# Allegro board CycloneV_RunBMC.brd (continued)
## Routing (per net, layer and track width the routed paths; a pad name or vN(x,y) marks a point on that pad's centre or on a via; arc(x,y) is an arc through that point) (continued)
ULPI_USBPHY_USB2B_DATA<1>: length 53.7
  TOP w0.112: R405.2 55.08,18.57 54.97,18.68 v1(54.97,19.04)
  TOP w0.127: UT7.A5 v1(17.98,11.21)
  L10-SIG w0.076: v1(17.98,11.21) 18.38,11.61 18.38,12.17 18.09,12.47 17.84,12.47 17.54,12.76 17.54,14.43 17.29,14.69 17.29,16.19 18.43,17.34 18.43,17.84 18.66,18.07 19.02,18.07 19.24,18.28 19.24,18.66 19.78,19.21 35.22,19.21 35.63,19.61 40.48,19.61 40.84,19.97 42.54,19.97 42.97,20.4 46.96,20.4 47.36,20 47.82,20 48.99,21.16 49.88,21.16 50.23,21.52 56.46,21.52 56.76,21.21 56.76,19.39 56.42,19.04 v1(54.97,19.04)
ULPI_USBPHY_USB2B_DATA<2>: length 53.3
  TOP w0.112: v1(54.78,17.55) 55,17.55 55.29,17.84 R404.2
  TOP w0.127: v1(19.58,17.61) 19.58,17.61 UT7.C13
  L10-SIG w0.076: v1(19.58,17.61) 19.96,17.99 35.38,17.99 36.34,18.95 40.79,18.95 41,18.74 41.62,18.74 41.7,18.81 41.7,19.13 41.77,19.21 41.93,19.21 42,19.13 42,18.81 42.08,18.74 42.91,18.74 43.22,19.06 50.79,19.06 50.87,19.13 50.87,19.84 50.97,19.94 51.17,19.94 51.25,19.87 51.25,18.07 51.35,17.97 51.48,17.97 51.56,18.04 51.56,19.87 51.63,19.94 51.78,19.94 51.86,19.87 51.86,18.5 51.96,18.4 52.09,18.4 52.16,18.47 52.16,19.87 52.24,19.94 52.39,19.94 52.47,19.87 52.47,19.03 52.55,18.95 52.7,18.95 52.77,19.03 52.77,19.87 52.85,19.94 53,19.94 53.08,19.87 53.08,19.03 53.16,18.95 53.31,18.95 53.38,19.03 53.38,19.87 53.46,19.94 53.61,19.94 53.69,19.87 53.69,19.03 53.77,18.95 53.92,18.95 53.99,19.03 53.99,19.87 54.07,19.94 54.3,19.94 54.37,19.87 54.37,17.68 54.51,17.55 v1(54.78,17.55)
ULPI_USBPHY_USB2B_DATA<3>: length 54.2
  TOP w0.112: v1(54.96,17.05) 55.48,17.05 R403.2
  TOP w0.127: UT7.B6 v1(18.79,12.02)
  L10-SIG w0.076: v1(54.96,17.05) 55.37,17.05 55.49,17.18 55.49,18.41 55.37,18.54 54.79,18.54 54.6,18.73 54.6,19.23 54.76,19.39 56.31,19.39 56.46,19.54 56.46,20.88 56.1,21.24 50.39,21.24 50.01,20.86 49.09,20.86 47.95,19.72 47.21,19.72 46.79,20.14 43.14,20.14 42.77,19.77 41.07,19.77 40.68,19.39 35.76,19.39 35.35,18.98 20.36,18.98 19.92,18.54 19.92,18.27 19.72,18.07 19.55,18.07 19.2,17.71 19.2,17.54 18.92,17.27 18.75,17.27 17.95,16.46 17.94,16.46 17.53,16.06 17.53,14.8 18.36,13.98 18.36,12.65 18.79,12.22 v1(18.79,12.02)
ULPI_USBPHY_USB2B_DATA<4>: length 53
  TOP w0.112: R402.2 55.09,16.41 54.98,16.52 v1(54.96,16.52)
  TOP w0.127: UT7.H13 v1(23.59,17.62)
  L10-SIG w0.076: v1(23.59,17.62) 24.02,17.19 28.79,17.19 28.86,17.26 28.86,17.63 28.94,17.71 29.09,17.71 29.17,17.63 29.17,17.26 29.24,17.19 35.11,17.19 36.68,18.76 40.2,18.76 40.48,18.47 42.95,18.47 43.22,18.75 45.57,18.75 45.65,18.67 45.65,18.1 45.72,18.02 45.88,18.02 45.95,18.1 45.95,18.67 46.03,18.75 46.67,18.75 46.74,18.67 46.74,18.57 46.82,18.5 46.97,18.5 47.05,18.57 47.05,18.67 47.12,18.75 49.46,18.75 49.54,18.67 49.54,17.76 49.62,17.68 49.77,17.68 49.85,17.76 49.85,18.67 49.92,18.75 50.07,18.75 50.15,18.67 50.15,17.76 50.23,17.68 50.38,17.68 50.46,17.76 50.46,18.67 50.53,18.75 50.77,18.75 50.95,18.57 50.95,17.73 50.59,17.38 46.35,17.38 46.27,17.3 46.27,17.1 46.35,17.02 50.67,17.02 51.3,17.66 51.76,17.66 52.72,18.62 54.04,18.62 54.15,18.52 54.15,17.25 54.86,16.54 54.93,16.54 v1(54.96,16.52)
ULPI_USBPHY_USB2B_DATA<5>: length 55.3
  TOP w0.127: UT7.A4 v1(18.01,10.44)
  L10-SIG w0.076: v1(18.01,10.44) 17.54,10.9 17.54,12.31 17.27,12.59 17.27,14.36 17,14.62 17,16.19 18.21,17.4 18.21,17.96 18.38,18.14 18.38,18.55 19.25,19.41 35.1,19.41 36.15,20.46 39.38,20.46 39.74,20.83 40.95,20.83 41.34,21.23 43.2,21.23 43.35,21.38 44.94,21.38 45.26,21.06 47.87,21.06 48.35,21.54 49.78,21.54 50.06,21.82 54.6,21.82 v1(54.68,21.9)
  BOTTOM w0.112: R400.2 58.85,17.15 59.15,17.46 59.15,18.18 59.04,18.29 58.26,18.29 54.68,21.87 v1(54.68,21.9)
ULPI_USBPHY_USB2B_DATA<6>: length 52.7
  TOP w0.127: UT7.H12 v1(23.59,16.82)
  L10-SIG w0.076: v1(49.12,18.19) 48.69,17.76 45.51,17.76 44.79,18.48 43.36,18.48 43.1,18.22 41.55,18.22 41.32,17.99 36.65,17.99 35.05,16.39 24.02,16.39 v1(23.59,16.82)
  BOTTOM w0.112: v1(49.12,18.19) 49.12,19.35 49.33,19.56 50.14,19.56 50.25,19.45 50.25,18.34 50.43,18.16 50.59,18.16 50.7,18.27 50.7,19.45 50.81,19.56 51.03,19.56 51.14,19.45 51.14,18.3 51.26,18.19 51.45,18.19 51.59,18.33 51.59,19.45 51.7,19.56 51.93,19.56 52.04,19.45 52.04,18.23 52.15,18.12 52.31,18.12 52.49,18.3 52.49,19.45 52.6,19.56 53.63,19.56 53.74,19.68 53.74,21.57 54.48,22.31 55.13,22.31 55.24,22.2 55.24,21.72 58.34,18.62 59.18,18.62 59.48,18.32 59.48,17.48 59.61,17.35 R401.2
ULPI_USBPHY_USB2B_DATA<7>: length 59
  TOP w0.127: UT7.B4 v1(18.82,10.44)
  L10-SIG w0.076: v1(54.67,22.7) 54.13,22.17 49.93,22.17 49.68,21.91 44.58,21.91 44.27,21.6 41.07,21.6 40.63,21.16 36.42,21.16 34.87,19.61 19.17,19.61 18.12,18.56 18.12,18.3 17.95,18.14 17.95,17.43 16.44,15.92 16.44,13.48 16.91,13.01 16.91,12.54 17.34,12.1 17.34,10.44 17.75,10.04 18.31,10.04 18.71,10.44 v1(18.82,10.44)
  BOTTOM w0.112: v1(54.67,22.7) 54.72,22.7 54.73,22.71 55.14,22.71 55.62,22.23 55.62,21.75 58.41,18.95 59.25,18.95 59.8,18.41 59.8,17.75 60.37,17.18 R399.2
ULPI_USBPHY_USB2B_DIR: length 52
  TOP w0.112: v1(53.05,17.81) 53.38,18.14 53.38,19.84 55.06,21.52 R409.2
  TOP w0.127: UT7.B11 v1(19.58,16.01)
  L10-SIG w0.076: v1(53.05,17.81) 53.05,17.71 53.81,16.95 53.81,15.93 54.04,15.7 55.21,15.7 55.29,15.63 55.29,15.19 55.21,15.12 53.63,15.12 53.55,15.19 53.55,15.47 53.47,15.55 53.32,15.55 53.25,15.47 53.25,15.19 53.17,15.12 53.02,15.12 52.94,15.19 52.94,15.47 52.86,15.55 52.71,15.55 52.64,15.47 52.64,15.19 52.56,15.12 52.41,15.12 52.33,15.19 52.33,15.47 52.25,15.55 52.1,15.55 52.03,15.47 52.03,15.19 51.95,15.12 51.75,15.12 51.67,15.19 51.67,15.45 51.59,15.52 51.44,15.52 51.37,15.45 51.37,15.19 51.29,15.12 49.32,15.12 48.51,14.31 44.49,14.31 43.25,15.55 42.26,15.55 41.93,15.22 40.28,15.22 39.83,14.77 36.76,14.77 35.16,13.16 24.33,13.16 24.04,13.45 24.04,13.79 23.82,14 23.5,14 22.05,15.45 21.84,15.45 21.53,15.75 21.53,16.14 21.26,16.41 20.24,16.41 19.83,16.01 v1(19.58,16.01)
ULPI_USBPHY_USB2B_DIR_R: length 3.4
  TOP w0.104: EU12.31 58.94,21.04 58.33,21.65 57.01,21.65 56.88,21.52 R409.1
ULPI_USBPHY_USB2B_NXT: length 52.9
  TOP w0.112: v1(53.43,16.79) 53.51,16.79 54.22,17.51 54.22,19.69 54.73,20.2 55.4,20.2 R407.2
  TOP w0.127: UT7.B9 v1(18.81,14.44)
  L10-SIG w0.076: v1(53.43,16.79) 53.43,16.19 53.18,15.93 49.55,15.93 49.35,15.73 49.24,15.73 49.06,15.92 48.95,15.92 48.84,15.81 48.84,15.7 49.03,15.52 49.03,15.41 48.18,14.56 47.81,14.56 47.74,14.64 47.74,15.12 47.66,15.19 47.51,15.19 47.43,15.12 47.43,14.64 47.35,14.56 47.2,14.56 47.13,14.64 47.13,15.12 47.05,15.19 46.9,15.19 46.82,15.12 46.82,14.64 46.75,14.56 46.59,14.56 46.52,14.64 46.52,15.12 46.44,15.19 46.29,15.19 46.21,15.12 46.21,14.64 46.14,14.56 45.98,14.56 45.91,14.64 45.91,15.12 45.83,15.19 45.68,15.19 45.6,15.12 45.6,14.64 45.53,14.56 45.37,14.56 45.3,14.64 45.3,15.12 45.22,15.19 45.07,15.19 44.99,15.12 44.99,14.64 44.92,14.56 44.62,14.56 43.38,15.8 40.99,15.8 40.71,16.08 40.33,16.08 39.89,15.64 38.91,15.64 38.91,15.65 36.82,15.65 35.15,13.98 24.28,13.98 23.92,14.33 23.92,14.61 23.74,14.79 23.41,14.79 23.23,14.97 23.23,15.34 22.93,15.65 22.93,16.11 22.4,16.64 19.98,16.64 19.73,16.39 19.37,16.39 19.2,16.21 19.2,15.89 18.92,15.62 18.66,15.62 18.43,15.4 18.43,14.83 v1(18.81,14.44)
ULPI_USBPHY_USB2B_NXT_R: length 1.9
  TOP w0.127: EU12.2 57.16,19.31 57.04,19.44 57.04,19.89 56.89,20.05 R407.1
ULPI_USBPHY_USB2B_R_DATA<0>: length 1.6
  TOP w0.127: R406.1 56.75,19 57.02,19 57.21,18.82 EU12.3
ULPI_USBPHY_USB2B_R_DATA<1>: length 1.5
  TOP w0.127: EU12.4 57.15,18.31 56.89,18.57 R405.1
ULPI_USBPHY_USB2B_R_DATA<2>: length 1.4
  TOP w0.127: R404.1 57.19,17.84 57.21,17.82 EU12.5
ULPI_USBPHY_USB2B_R_DATA<3>: length 1.4
  TOP w0.127: EU12.6 57.08,17.31 56.89,17.13 R403.1
ULPI_USBPHY_USB2B_R_DATA<4>: length 1.6
  TOP w0.127: R402.1 56.94,16.41 57.07,16.54 57.07,16.69 57.19,16.82 EU12.7
ULPI_USBPHY_USB2B_R_DATA<5>: length 1.8
  TOP w0.104: v1(58.36,14.92) 58.36,15.02 58.44,15.1 EU12.9
  BOTTOM w0.112: v1(58.36,14.92) 58.36,15.25 R400.1
ULPI_USBPHY_USB2B_R_DATA<6>: length 1.8
  TOP w0.104: EU12.10 58.94,15.02 58.97,14.99 v1(58.97,14.95)
  BOTTOM w0.112: R401.1 59.61,15.68 58.97,15.04 v1(58.97,14.95)
ULPI_USBPHY_USB2B_R_DATA<7>: length 1.4
  TOP w0.104: EU12.13 v1(60.44,15.02)
  BOTTOM w0.112: v1(60.44,15.02) 60.44,15.66 R399.1
ULPI_USBPHY_USB2B_STP: length 54.7
  TOP w0.104: v1(59.94,21.49) 59.94,21.49 EU12.29
  TOP w0.127: UT7.B8 v1(18.79,13.62)
  L10-SIG w0.076: v1(59.94,21.49) 59.94,19.89 56.05,16.01 54.84,16.01 54.58,16.26 54.58,16.49 53.79,17.28 53.79,17.94 53.54,18.19 52.65,18.19 51.8,17.34 51.36,17.34 50.72,16.69 46.2,16.69 45.55,17.34 44.71,17.34 44.53,17.52 43.36,17.52 43.02,17.18 36.24,17.18 34.69,15.63 24.22,15.63 24.02,15.83 24.02,16.08 23.64,16.46 23.34,16.46 23.06,16.74 23.06,16.95 22.78,17.23 19.46,17.23 19.21,16.98 19.21,16.74 18.92,16.45 18.67,16.45 18.26,16.03 18.26,14.46 18.79,13.92 v1(18.79,13.62)
  BOTTOM w0.112: R410.2 v1(59.94,21.49)
UNNAMED_60_MPM3632_I11_OUTSENSE: length 1.5
  TOP w0.254: UT8.10 5.84,17.33 6.32,17.81 RT69.1
UNNAMED_60_MPM3632_I18_OUTSENSE: length 1.7
  TOP w0.254: UT5.10 5.84,22.92 v2(6.15,23.23)
  BOTTOM w0.508: v2(6.15,23.23) 6.13,23.24 RB81.1
UNNAMED_61_MPM3833_I38_OUTS: length 1.2
  TOP w0.203: RT66.1 12.49,19.08 12.72,19.31 UT6.3
USB2_PCH_SMC_DN: length 12.2
  TOP w0.091: v1(56.94,6.12) 56.95,6.12 56.95,6.1 56.97,6.07 56.97,6.03 57.04,5.96 57.04,3.3 57.43,2.92 JT3.217 ; U8A6.19 59.98,9.57 59.99,9.56 60.44,9.56 60.8,9.2 60.8,8.28 60.29,7.77 60.29,7.27 60.17,7.15 60.17,7.12 60.07,7.02 v1(60.07,6.71)
  L3-SIG w0.091: v1(56.94,6.12) 57.04,6.21 59.48,6.21 59.98,6.71 v1(60.07,6.71)
USB2_PCH_SMC_DP: length 12.1
  TOP w0.091: v1(59.76,7.24) 59.83,7.24 59.99,7.4 59.99,7.9 60.5,8.41 60.5,9.07 60.31,9.25 60.12,9.25 59.93,9.07 U8A6.18 ; JT3.219 57.93,2.99 57.84,3.08 57.72,3.08 57.71,3.1 57.71,3.1 57.49,3.32 57.49,3.32 57.35,3.46 57.35,4.71 57.47,4.83 57.47,5.11 57.35,5.23 57.35,5.4 57.47,5.52 57.47,5.72 57.37,5.82 57.37,6.44 57.26,6.56 57.09,6.56 v1(57,6.65)
  L3-SIG w0.091: v1(57,6.65) 57.02,6.63 59.31,6.63 59.76,7.09 v1(59.76,7.24)
USB2_USB2B_DN: length 18.9
  TOP w0.091: JT3.223 58.93,2.85 59.02,2.95 59.02,5.24 59.51,5.72 59.94,5.72 61.08,6.87 v1(61.08,7.02)
  TOP w0.104: v1(63.27,17.23) 63.24,17.23 63.15,17.31 EU12.19
  L5-SIG w0.074: v1(61.08,7.02) 61.26,7.19 61.26,12.17 61.79,12.71 61.79,16.64 62.27,17.12 62.55,17.12 62.81,17.12 62.92,17.23 v1(63.27,17.23)
USB2_USB2B_DP: length 18.6
  TOP w0.091: JT3.225 59.43,2.85 59.33,2.95 59.33,5.11 59.63,5.42 60.06,5.42 61.66,7.02 v1(61.68,7.02)
  TOP w0.104: v1(63.26,16.69) 63.26,16.71 63.16,16.82 EU12.18
  L5-SIG w0.074: v1(61.68,7.02) 61.56,7.13 61.56,12.05 62.1,12.58 62.1,16.52 62.39,16.81 62.54,16.81 62.81,16.81 62.92,16.7 v1(63.26,16.69)
V_BMC_DAC_IOB: length 131.2
  TOP w0.104: v1(50.54,23.63) 50.95,23.22 50.95,21.29 51.12,21.11 R423.2 R417.2 R424.2 R420.2 53.69,20.66 53.48,20.45 52.87,20.45 52.67,20.25 R429.1
  L5-SIG w0.076: v1(50.54,23.63) 49.47,23.63 49.02,24.08 49.02,34.44 48.52,34.94 48.52,37.43 47.72,38.23 47.72,47.61 46.91,48.42 2.89,48.42 1.03,46.56 1.03,26.35 3.52,23.86 4.72,23.86 4.98,23.61 4.98,15.76 3.37,14.15 3.37,6.94 4.01,6.3 4.01,5.59 3.42,5.01 v1(3.42,3.94)
  BOTTOM w0.112: JT3.12 4.18,2.66 4.64,3.12 4.64,3.97 4.32,4.29 3.65,4.29 3.42,4.07 v1(3.42,3.94)
V_BMC_DAC_IOG: length 130.1
  TOP w0.104: v1(49.12,20.4) 48.94,20.4 48.75,20.21 48.75,19.5 48.25,19 ; R428.2 R422.2 R427.2 R419.2 49.16,19 48.25,19 ; R431.1 48.25,19
  L5-SIG w0.076: v1(3.98,3.89) 4.37,3.89 4.69,4.21 4.69,6 3.63,7.07 3.63,14.05 5.23,15.65 5.23,23.7 4.82,24.1 3.99,24.1 3.4,24.69 3.4,26.37 3.04,26.73 3.04,31.85 2.47,32.42 2.47,34.56 1.31,35.72 1.31,46.37 3.06,48.11 46.63,48.11 47.48,47.26 47.48,38.13 48.22,37.4 48.22,34.79 48.8,34.21 48.8,27.15 47.97,26.32 47.97,22.69 49.12,21.54 v1(49.12,20.4)
  BOTTOM w0.112: v1(3.98,3.89) 4.01,3.87 4.01,3.86 4.37,3.5 4.37,3.18 4.14,2.96 3.85,2.96 3.68,2.78 JT3.10
V_BMC_DAC_IOR: length 125.4
  TOP w0.104: v1(47.64,21.42) 47.64,21.39 47.92,21.11 R421.2 ; R426.2 R425.2 R418.2 R421.2 ; R430.1 48.22,21.1 R421.2
  L5-SIG w0.076: v1(5.35,5.19) 5.35,5.75 3.88,7.22 3.88,13.96 5.47,15.56 5.47,23.72 5.66,23.91 5.66,24.9 5.25,25.3 5.25,26.4 3.3,28.35 3.3,31.94 2.71,32.52 2.71,42.96 1.54,44.13 1.54,46.26 3.09,47.81 46.32,47.81 47.24,46.89 47.24,38.44 47.22,38.43 47.22,38.05 47.95,37.32 47.95,29.09 47.36,28.5 47.36,21.67 47.62,21.42 v1(47.64,21.42)
  BOTTOM w0.112: v1(5.35,5.19) 5.08,5.19 4.9,5 4.9,3.04 4.68,2.82 JT3.14
V_BMC_DDC_SCL: length 52.8
  TOP w0.127: UT7.W24 v1(32.33,26.36)
  L8-SIG w0.076: v1(6.19,4.55) 6.7,5.06 7.79,5.06 7.99,4.86 8.78,4.86 9.11,5.19 9.11,6.83 9.92,7.64 9.92,11.46 10.61,12.15 10.61,12.4 11.32,13.11 11.32,15.12 13.4,17.2 13.4,21.21 15.12,22.92 19.35,22.92 19.43,22.85 23.75,22.85 23.97,23.07 23.97,23.31 24.29,23.63 24.51,23.63 24.8,23.92 24.8,24.14 25.83,25.17 25.84,25.17 26.89,26.22 28.49,26.22 29.05,26.78 31.91,26.78 v1(32.33,26.36)
  BOTTOM w0.089: v1(32.33,26.36) 32.33,26.42 32.68,26.78 33.55,26.78 33.61,26.84 33.61,30.7 33.55,30.76
  BOTTOM w0.112: JT3.20 6.18,2.89 6.52,3.23 6.52,3.25 6.58,3.31 6.58,4.17 v1(6.19,4.55) ; 33.55,30.76 33.45,30.87 R433.2
V_BMC_DDC_SDA: length 54
  TOP w0.127: UT7.AB25 v1(34.78,27.21)
  L8-SIG w0.076: v1(6.22,5.11) 6.37,5.26 7.89,5.26 8.1,5.06 8.68,5.06 8.91,5.29 8.91,6.92 9.72,7.73 9.72,11.33 9.43,11.63 9.43,13.26 10.99,14.82 10.99,15.29 12.13,16.44 12.13,20.23 15.32,23.41 18.11,23.41 18.31,23.6 23.68,23.6 24.02,23.93 24.02,24.16 24.25,24.39 24.66,24.39 26.92,26.65 28.57,26.65 29.51,27.59 33.85,27.59 33.85,27.59 34.15,27.59 34.15,27.59 34.4,27.59 v1(34.78,27.21)
  BOTTOM w0.089: v1(34.78,27.21) 34.38,27.61 34.38,30.67 34.28,30.76
  BOTTOM w0.112: v1(6.22,5.11) 6.6,4.73 6.6,4.51 6.82,4.28 6.82,3.15 6.68,3.01 JT3.22 ; R432.2 34.21,30.84 34.28,30.76
V_BMC_HSYN: length 28.9
  L5-SIG w0.076: v1(14.22,5.31) 14.13,5.31 13.99,5.16 13.58,5.16 12.93,4.51 12.93,3.18 12,2.24 6.26,2.24 5.56,2.94 v1(5.56,3.33)
  BOTTOM w0.112: JT3.16 5.18,2.94 v1(5.56,3.33)
  BOTTOM w0.114: v1(14.22,5.31) 14.27,5.35 14.27,5.49 14.34,5.57 14.34,5.59 14.65,5.9 14.65,6.74 15.41,7.5 15.41,8.64 16.16,9.39 17.37,9.39 17.54,9.57 17.54,10.56 17.83,10.85 18.93,10.85 19.18,11.09 19.18,16.08 18.82,16.44 18.61,16.44 R415.2
V_BMC_HSYN_R: length 6
  TOP w0.089: UT7.E11 v1(21.97,16.01)
  BOTTOM w0.114: R415.1 18.15,17.81 18.38,18.04 19.83,18.04 20.01,17.86 20.01,17.47 20.27,17.2 21.51,17.2 21.97,16.74 v1(21.97,16.01)
V_BMC_VSYN: length 29.2
  L5-SIG w0.076: v1(14.83,5.31) 14.45,5.69 14.03,5.69 13.77,5.43 12.27,5.43 11.86,5.02 11.86,3.18 11.3,2.62 6.85,2.62 6.14,3.33 v1(6.14,3.42)
  BOTTOM w0.112: JT3.18 5.68,2.87 6.14,3.33 v1(6.14,3.42)
  BOTTOM w0.114: v1(14.83,5.31) 14.83,5.7 14.9,5.78 14.9,6.18 15.06,6.33 15.59,6.33 15.72,6.46 15.72,8.58 16.29,9.15 17.62,9.15 18.46,9.99 19.91,9.99 20.01,10.09 20.01,16.36 20.26,16.62 R416.2
V_BMC_VSYN_R: length 1.2
  TOP w0.089: UT7.D11 v1(21.17,16.02)
  BOTTOM w0.114: R416.1 21.15,16.03 v1(21.17,16.02)
V_M_BMC_DDR3_BA0: length 54.5
  TOP w0.127: U4.M2 v1(42.55,43.16) ; UT7.A27 18.07,29.52 v1(17.39,29.52) ; U3.M2 v1(32.77,43.21) ; U2.M2 v1(22.93,43.23)
  L3-SIG w0.076: v1(17.39,29.52) 16.94,29.97 16.94,31.11 16.48,31.58 16.48,33 16.07,33.41 16.07,37.95 15.98,38.04 15.68,38.04 15.59,38.13 15.59,38.31 15.68,38.4 15.98,38.4 16.07,38.49 16.07,38.67 15.98,38.75 15.68,38.75 15.59,38.84 15.59,39.02 15.68,39.11 15.98,39.11 16.07,39.2 16.07,39.55 15.7,39.92 15.7,42.28 16.27,42.86 19.38,42.86 19.46,42.94 19.46,43.38 19.55,43.46 19.73,43.46 19.82,43.38 19.82,42.94 19.91,42.86 20.79,42.86 20.87,42.94 20.87,43.22 20.96,43.31 21.14,43.31 21.23,43.22 21.23,42.94 21.32,42.86 22.55,42.86 v1(22.93,43.23) 23.38,42.78 32.35,42.78 v1(32.77,43.21) 33.17,42.8 42.19,42.8 v1(42.55,43.16)
  BOTTOM w0.112: v1(42.55,43.16) 42.16,42.78 41.13,42.78 40.68,43.22 40.68,47.95 RB6.1
V_M_BMC_DDR3_BA1: length 59.5
  TOP w0.127: U4.N8 v1(36.95,43.96) ; v1(23.58,28.03) 23.58,28.01 UT7.H25 ; U2.N8 v1(17.33,44.03) ; U3.N8 v1(27.17,44.01)
  L10-SIG w0.076: v1(23.58,28.03) 23.23,28.38 23.23,29.91 23.02,30.12 21.88,30.12 21.74,30.26 21.74,30.89 21.56,31.07 21.08,31.07 20.54,31.6 20.54,37.78 20.45,37.86 19.59,37.86 19.5,37.95 19.5,38.13 19.59,38.22 20.45,38.22 20.54,38.31 20.54,38.49 20.45,38.58 19.49,38.58 19.4,38.66 19.4,38.84 19.49,38.93 20.45,38.93 20.54,39.02 20.54,39.2 20.45,39.29 19.41,39.29 19.32,39.38 19.32,39.55 19.41,39.64 20.45,39.64 20.54,39.73 20.54,39.95 20.45,40.04 16.2,40.04 15.82,40.42 15.82,43.95 16.26,44.39 16.96,44.39 v1(17.33,44.03) 17.68,44.38 18.87,44.38 19.65,43.59 26.76,43.59 v1(27.17,44.01) 27.58,43.6 36.59,43.6 v1(36.95,43.96)
  BOTTOM w0.112: RB11.1 37.56,47.83 37.74,47.66 37.97,47.66 38.66,46.97 38.68,46.97 39.01,46.63 39.01,45.43 37.94,44.35 37.34,44.35 v1(36.95,43.96)
V_M_BMC_DDR3_BA2: length 58.2
  TOP w0.127: U3.M3 v1(31.97,43.21) ; v1(22.8,28.03) 22.8,27.99 UT7.G25 ; U2.M3 v1(22.13,43.23) ; U4.M3 v1(41.75,43.16)
  L8-SIG w0.076: v1(41.75,43.16) 41.37,42.79 32.39,42.79 v1(31.97,43.21) 31.6,42.83 22.52,42.83 v1(22.13,43.23) 21.55,43.23 21.25,42.93 21.25,41.23 21.71,40.77 21.71,40.47 21.82,40.35 22.79,40.35 22.9,40.24 22.9,40.01 22.79,39.89 21.82,39.89 21.71,39.78 21.71,39.02 21.89,38.84 22.42,38.84 22.52,38.74 22.52,38.14 22.41,38.03 21.81,38.03 21.71,37.93 21.71,37.37 21.84,37.24 22.45,37.24 22.55,37.14 22.55,36.58 22.4,36.43 21.75,36.43 21.6,36.28 21.06,36.28 20.95,36.16 20.95,35.76 21.06,35.64 22.41,35.64 22.52,35.53 22.52,34.97 22.41,34.85 21.06,34.85 20.95,34.74 20.95,34.13 21.06,34.02 22.82,34.02 22.93,33.9 22.93,33.09 22.82,32.97 21.06,32.97 20.95,32.86 20.95,32.03 20.11,31.2 20.11,30.41 20.8,29.72 20.8,29.47 21.08,29.19 22.26,29.19 22.37,29.08 22.37,28.38 22.72,28.03 v1(22.8,28.03)
  BOTTOM w0.112: RB5.1 41.12,47.58 40.95,47.41 40.95,44.46 40.96,44.45 40.96,43.95 v1(41.75,43.16)
V_M_BMC_DDR3_CAS_N: length 50.9
  TOP w0.127: v1(17.96,28.83) 17.96,28.81 18.36,28.41 UT7.A26 ; U4.K3 v1(41.75,41.56) ; U2.K3 v1(22.13,41.63) ; U3.K3 v1(31.97,41.61)
  L3-SIG w0.076: v1(41.75,41.56) 41.33,41.98 32.35,41.98 v1(31.97,41.61) 31.55,42.03 22.53,42.03 v1(22.13,41.63) 21.74,42.02 21.29,42.02 21.2,42.11 21.2,42.36 21.11,42.45 20.93,42.45 20.84,42.36 20.84,41.93 20.75,41.84 20.62,41.84 20.53,41.93 20.53,42.32 20.4,42.45 20.22,42.45 20.13,42.36 20.13,41.93 20.04,41.84 19.86,41.84 19.77,41.93 19.77,42.41 19.69,42.5 19.51,42.5 19.42,42.41 19.42,42.11 19.33,42.02 16.27,42.02 16.12,41.86 16.12,40.24 16.95,39.41 16.95,38.29 17.04,38.21 17.18,38.21 17.27,38.12 17.27,37.94 17.18,37.85 17.04,37.85 16.95,37.76 16.95,37.58 17.04,37.49 17.18,37.49 17.27,37.41 17.27,37.23 17.18,37.14 17.04,37.14 16.95,37.05 16.95,36.87 17.04,36.78 17.18,36.78 17.27,36.69 17.27,36.52 17.18,36.43 17.04,36.43 16.95,36.34 16.95,36.16 17.04,36.07 17.18,36.07 17.27,35.98 17.27,35.81 17.18,35.72 17.04,35.72 16.95,35.63 16.95,35.45 17.04,35.36 17.18,35.36 17.27,35.27 17.27,35.09 17.18,35.01 17.04,35.01 16.95,34.92 16.95,32.48 17.32,32.11 17.32,30.14 17.96,29.49 v1(17.96,28.83)
  BOTTOM w0.112: RB40.1 43.97,42.4 43.52,41.95 42.13,41.95 v1(41.75,41.56)
V_M_BMC_DDR3_CKE: length 61
  TOP w0.127: UT7.L28 26,30.39 v1(26,30.41) ; U2.K9 v1(16.53,41.63) ; U3.K9 v1(26.37,41.61) ; U4.K9 v1(36.15,41.56)
  L10-SIG w0.076: v1(26,30.41) 25.73,30.67 25.73,31.16 25.11,31.78 22.04,31.78 21.74,32.09 21.74,34.7 21.84,34.8 22.45,34.8 22.55,34.91 22.55,35.54 22.45,35.64 21.58,35.64 21.46,35.77 21.46,36.28 21.61,36.43 22.37,36.43 22.5,36.56 22.5,37.11 22.37,37.24 21.63,37.24 21.48,37.39 21.48,37.92 21.57,38 22.41,38 22.5,38.09 22.5,38.78 22.41,38.87 21.56,38.87 21.43,38.99 21.43,39.76 21.58,39.91 24.07,39.91 24.28,40.11 24.28,40.37 24.17,40.47 21.43,40.47 20.64,41.26 16.9,41.26 v1(16.53,41.63) 16.94,42.04 21.18,42.04 21.98,41.24 26.01,41.24 v1(26.37,41.61) 26.78,41.19 33.73,41.19 33.75,41.18 35.76,41.18 v1(36.15,41.56)
  BOTTOM w0.112: RB20.1 RB19.1 33.24,47.16 33.33,47.08 34,47.08 34.56,46.51 34.56,43.15 v1(36.15,41.56)
V_M_BMC_DDR3_CLK_DN: length 56.6
  TOP w0.122: v1(18.93,41.63) U2.K7 ; U3.K7 v1(28.77,40.81)
  TOP w0.127: U4.K7 v1(38.55,40.76) ; UT7.N20 v1(27.58,24.01)
  L5-SIG w0.076: 17.62,30.03 17.69,30.03 18.23,29.49 18.23,29.04 18.3,28.97 18.3,28.53 18.5,28.33 19.18,28.33 19.98,27.53 22.12,27.53 22.98,26.68 23.23,26.68 23.31,26.6 23.31,26.35 23.48,26.18 23.83,26.18 24,26.35 24,26.6 24.07,26.68 24.67,26.68 25.01,26.33 25.01,25.48 25.32,25.18 27.04,25.18 27.12,25.1 27.12,24.4 27.3,24.21 27.49,24.21 27.58,24.13 v1(27.58,24.01)
  L5-SIG w0.094: v1(38.55,40.76) 38.38,40.59 37.36,40.59 37.08,40.32 29.26,40.32 v1(28.77,40.81) 28.41,40.44 21.6,40.44 20.61,41.43 19.12,41.43 v1(18.93,41.63) 18.76,41.46 18.06,41.46 17.85,41.25 17.85,39.85 17.75,39.76 17.18,39.76 17.06,39.88 17.06,40.16 16.8,40.42 16.08,40.42 15.54,39.88 15.54,30.09 15.98,29.65 16.59,29.65 16.97,30.03 17.62,30.03
  BOTTOM w0.119: RB47.2 39.38,40.89 39.03,40.54 38.77,40.54 v1(38.55,40.76)
V_M_BMC_DDR3_CLK_DP: length 57
  TOP w0.127: U4.J7 v1(38.55,39.96) ; U3.J7 v1(28.77,40.01) ; U2.J7 v1(18.93,40.83) ; UT7.N21 v1(27.58,24.81)
  L5-SIG w0.076: v1(27.58,24.81) 27.77,24.61 27.77,24.43 27.71,24.36 27.37,24.36 27.27,24.46 27.27,25.28 27.12,25.43 26.94,25.43 26.84,25.33 26.64,25.33 26.51,25.45 26.41,25.45 26.28,25.33 26.05,25.33 25.9,25.48 25.77,25.48 25.62,25.33 25.38,25.33 25.16,25.54 25.16,25.76 25.29,25.89 25.29,26.04 25.16,26.17 25.16,26.55 25.04,26.68 24.89,26.68 24.73,26.83 24.01,26.83 23.84,26.66 23.84,26.41 23.77,26.33 23.54,26.33 23.46,26.41 23.46,26.66 23.3,26.83 23.04,26.83 22.19,27.68 20.04,27.68 19.24,28.48 18.56,28.48 18.45,28.59 18.45,29.03 18.38,29.1 18.38,29.55 17.8,30.14 17.8,30.18 17.72,30.26 17.62,30.26
  L5-SIG w0.094: v1(38.55,39.96) 38.55,40.04 38.22,40.37 37.45,40.37 37.17,40.09 29.24,40.09 29.16,40.01 v1(28.77,40.01) 28.57,40.21 21.51,40.21 20.52,41.2 19.3,41.2 v1(18.93,40.83) 18.57,41.18 18.15,41.18 18.08,41.1 18.08,39.76 17.85,39.53 17.09,39.53 16.83,39.78 16.83,40.06 16.71,40.19 16.17,40.19 15.77,39.78 15.77,30.18 16.07,29.88 16.5,29.88 16.88,30.26 17.62,30.26
  BOTTOM w0.119: RB47.1 39.22,40 39.01,40.21 38.8,40.21 v1(38.55,39.96)
V_M_BMC_DDR3_CS_N: length 58.6
  TOP w0.127: U4.L2 v1(42.55,42.36) ; U3.L2 v1(32.77,42.41) ; UT7.L21 v1(25.98,24.81) ; U2.L2 v1(22.93,42.43)
  L5-SIG w0.076: v1(42.55,42.36) 42.13,42.78 33.15,42.78 v1(32.77,42.41) 32.35,42.83 23.33,42.83 v1(22.93,42.43) 22.55,42.8 16.38,42.8 15.11,41.53 15.11,29.57 17.83,26.85 17.99,26.85 18.03,26.8 21.3,26.8 21.62,26.48 21.62,26.26 21.88,25.99 23.71,25.99 24.07,25.63 24.07,25.45 24.32,25.2 24.61,25.2 25,24.81 v1(25.98,24.81)
  BOTTOM w0.112: v1(42.55,42.36) 42.93,42.75 43.51,42.75 43.69,42.93 RB39.1
V_M_BMC_DDR3_DM_0: length 25.3
  TOP w0.127: v1(23.59,30.87) 23.59,30.42 UT7.G28 ; U2.E7 18.75,37.23 v1(19.17,37.65)
  L3-SIG w0.076: v1(19.17,37.65) 20.12,37.65 20.21,37.73 20.21,38.63 20.3,38.72 20.55,38.72 20.64,38.63 20.64,38.42 20.73,38.33 20.91,38.33 21,38.42 21,38.74 21.1,38.84 22.35,38.84 22.57,39.07 22.57,39.43 22.9,39.76 24.83,39.76 24.94,39.65 24.94,39.39 25,39.32 25.24,39.32 25.34,39.43 25.34,39.68 25.42,39.76 25.89,39.76 25.98,39.67 25.98,39.08 25.89,38.99 25.38,38.99 25.29,38.91 25.29,31.5 25.39,31.4 25.39,30.92 24.76,30.28 24.76,29.39 24.58,29.22 24.15,29.22 24,29.37 24,30.46 v1(23.59,30.87)
V_M_BMC_DDR3_DM_1: length 21.8
  TOP w0.127: U2.D3 v1(21.31,36.84) ; UT7.P28 v1(28.38,30.41)
  L5-SIG w0.076: v1(28.38,30.41) 28.38,30.52 28.67,30.82 28.67,30.9 28.86,31.09 28.86,31.49 29.91,32.54 29.91,37.88 29.79,38 25.69,38 25.57,38.12 25.57,38.73 25.46,38.84 25.23,38.84 25.12,38.73 25.12,38.12 25,38 24.77,38 24.66,38.12 24.66,38.75 24.55,38.87 24.32,38.87 24.2,38.75 24.2,38.12 24.09,38 21.63,38 21.31,37.68 v1(21.31,36.84)
V_M_BMC_DDR3_DM_2: length 24.2
  TOP w0.127: v1(33.15,30.41) 32.78,30.03 UT7.W28 ; v1(28.82,37.63) 28.4,37.2 U3.E7
  L10-SIG w0.076: v1(33.15,30.41) 34.88,32.14 35.32,32.14 36.59,33.41 36.59,39.43 36.44,39.58 35.55,39.58 35.46,39.67 35.46,40.3 35.37,40.39 35.19,40.39 35.11,40.3 35.11,39.44 35.02,39.35 34.84,39.35 34.75,39.44 34.75,40.3 34.66,40.39 34.48,40.39 34.39,40.3 34.39,39.67 34.31,39.58 31.97,39.58 31.62,39.22 29.84,39.22 28.82,38.2 v1(28.82,37.63)
V_M_BMC_DDR3_DM_3: length 23.7
  TOP w0.127: UT7.AB28 35.18,30.82 v1(34.8,31.2) ; U3.D3 31.98,36.81 v1(33.6,36.81)
  L3-SIG w0.076: v1(33.6,36.81) 33.14,37.27 33.14,37.8 32.96,37.98 31.74,37.98 31.59,38.13 31.59,38.69 31.69,38.79 32.89,38.79 33.14,39.05 33.14,39.68 33.42,39.96 34.75,39.96 34.83,39.87 34.83,39.03 34.92,38.94 35.1,38.94 35.19,39.03 35.19,39.87 35.28,39.96 35.57,39.96 35.65,39.87 35.65,39.1 35.99,38.77 36.16,38.77 36.52,38.41 36.52,33.43 36.09,33 35.91,33 34.8,31.89 v1(34.8,31.2)
V_M_BMC_DDR3_DM_4: length 33.2
  TOP w0.127: v1(40.62,36.73) 40.62,33.05 40.49,32.92 38.67,32.92 38.54,33.05 38.54,36.77 U4.E7 ; UT7.AE28 v1(37.17,30.42)
  L5-SIG w0.076: v1(37.17,30.42) 37.44,30.14 37.52,30.14 37.66,30 39.72,30 40.51,30.79 40.51,31.25 40.63,31.37 40.92,31.37 41.04,31.25 41.04,30.9 41.15,30.79 41.43,30.79 41.55,30.9 41.55,31.25 41.67,31.37 41.88,31.37 42,31.25 42,30.89 42.15,30.74 42.31,30.74 42.46,30.89 42.46,32.29 42.13,32.62 41.19,32.62 41.09,32.72 41.09,32.97 41.24,33.13 42.02,33.13 42.13,33.24 42.13,33.89 42.03,33.99 41.2,33.99 41.12,34.07 41.12,34.65 41.22,34.75 42.84,34.75 42.94,34.85 42.94,36.58 42.82,36.71 42.28,36.71 42.16,36.58 42.16,35.69 42,35.54 40.96,35.54 40.62,35.89 v1(40.62,36.73)
V_M_BMC_DDR3_DQ<0>: length 30.2
  TOP w0.127: U2.E3 v1(22.13,36.83) ; UT7.J25 v1(24.38,28.01)
  L3-SIG w0.076: v1(22.13,36.83) 22.31,36.83 22.73,37.24 23.95,37.24 24.1,37.09 24.1,32.49 23.08,31.48 22.71,31.48 22.62,31.39 22.62,30.54 22.78,30.38 23.62,30.38 23.67,30.33 23.67,30.05 23.59,29.98 22.94,29.98 22.85,29.89 22.85,29.37 23.01,29.22 23.84,29.22 23.97,29.09 23.97,28.5 23.89,28.43 23.31,28.43 23.2,28.31 23.2,27.68 23.31,27.56 24.22,27.56 25.09,26.7 25.39,26.7 25.98,26.12 25.98,25.27 26.07,25.18 26.28,25.18 26.41,25.05 26.41,23.61 26.5,23.53 27.06,23.53 27.15,23.61 27.15,25.57 27.06,25.66 26.76,25.66 26.64,25.79 26.64,26.22 26.03,26.83 25.8,26.83 25.62,27.01 25.62,27.5 25.53,27.59 24.8,27.59 v1(24.38,28.01)
V_M_BMC_DDR3_DQ<1>: length 29.8
  TOP w0.127: U2.F7 v1(18.95,38.45) ; UT7.J24 24.5,26.53 24.5,26.37 v1(24.43,26.29)
  L3-SIG w0.076: v1(24.43,26.29) 24.83,25.89 24.83,24.45 24.75,24.36 24.11,24.36 24.02,24.45 24.02,25.89 23.89,26.02 23.22,26.02 23.13,25.93 23.13,24.02 23.04,23.93 22.87,23.93 22.78,24.02 22.78,25.56 22.39,25.96 21.86,25.96 21.63,26.19 21.63,26.55 21.66,26.58 21.66,26.8 21.58,26.88 21.58,29.95 21.3,30.23 20.85,30.23 20.64,30.43 20.64,30.92 20.69,30.97 20.69,31.58 20.19,32.09 20.19,37.04 20.01,37.22 18.97,37.22 18.79,37.39 18.79,37.85 18.99,38.05 19.78,38.05 19.88,38.16 19.88,39.29 19.79,39.38 19.54,39.38 19.45,39.29 19.45,38.58 19.33,38.45 v1(18.95,38.45)
V_M_BMC_DDR3_DQ<2>: length 25.6
  TOP w0.127: U2.F2 v1(22.93,37.63) ; v1(22.21,30.69) 21.71,30.69 21.58,30.57 UT7.E28
  L3-SIG w0.076: v1(22.93,37.63) 22.73,37.63 22.29,37.19 21.77,37.19 21.68,37.1 21.68,36.53 21.77,36.44 23.27,36.44 23.36,36.35 23.36,34.14 23.21,33.99 22.95,33.99 22.88,33.91 22.88,33.72 22.97,33.64 23.3,33.64 23.39,33.55 23.39,33.34 23.3,33.25 22.65,33.25 22.5,33.41 22.5,35.58 22.41,35.67 21.86,35.67 21.74,35.79 21.74,36.02 21.66,36.1 21.39,36.1 21.33,36.04 21.33,35.4 21.42,35.31 21.6,35.31 21.68,35.22 21.68,33.64 21.6,33.55 21.49,33.55 21.41,33.46 21.41,33.28 21.49,33.19 21.85,33.19 22.14,32.9 23.53,32.9 23.59,32.84 23.59,32.61 23.53,32.54 21.7,32.54 21.61,32.45 21.61,32.28 21.7,32.19 22.9,32.19 23.01,32.09 23.01,31.93 22.9,31.83 22.37,31.83 22.21,31.68 v1(22.21,30.69)
V_M_BMC_DDR3_DQ<3>: length 23.7
  TOP w0.127: UT7.D27 v1(20.38,29.61) ; U2.F8 v1(18.13,37.63)
  L3-SIG w0.076: v1(18.13,37.63) 18.13,37.37 18.51,36.99 18.51,36.53 18.64,36.4 19.35,36.4 19.42,36.33 19.42,35.71 19.34,35.62 18.61,35.62 18.54,35.54 18.54,34.89 18.62,34.8 19.32,34.8 19.48,34.65 19.48,33.58 19.41,33.52 19.21,33.52 19.14,33.58 19.14,33.99 19.07,34.07 18.57,34.07 18.48,33.98 18.48,33.28 18.57,33.19 19.36,33.19 19.45,33.1 19.45,32.92 19.36,32.83 18.12,32.83 18.03,32.74 18.03,32.58 18.12,32.49 19.31,32.49 19.4,32.4 19.4,32.2 19.33,32.14 18.32,32.14 18.23,32.05 18.23,31.83 18.32,31.74 18.78,31.74 18.87,31.65 18.87,31.48 18.78,31.39 18.5,31.39 18.41,31.3 18.41,30.05 18.51,29.95 18.66,29.95 18.76,30.05 18.76,30.26 18.84,30.34 19.04,30.34 19.12,30.26 19.12,29.99 19.21,29.9 19.37,29.9 19.5,30.03 19.5,30.27 19.59,30.36 19.75,30.36 19.86,30.26 19.86,29.95 19.93,29.88 20.14,29.88 20.2,29.94 20.2,30.19 20.26,30.26 20.54,30.26 20.77,30.03 20.77,29.49 20.69,29.42 20.57,29.42 v1(20.38,29.61)
V_M_BMC_DDR3_DQ<4>: length 30.2
  TOP w0.127: U2.H3 v1(22.13,39.23) ; UT7.J26 v1(24.38,28.81)
  L3-SIG w0.076: v1(24.38,28.81) 24.2,28.63 24.2,28.47 24.29,28.38 24.69,28.38 24.78,28.47 24.78,28.99 24.96,29.16 25.47,29.16 25.57,29.27 25.57,29.75 25.34,29.98 25.18,29.98 25.09,30.07 25.09,30.26 25.16,30.33 25.34,30.33 25.77,30.76 25.77,31.53 25.65,31.65 25.65,37.69 25.74,37.78 26.03,37.78 26.11,37.86 26.11,38.04 26.03,38.13 25.66,38.13 25.57,38.22 25.57,38.6 25.66,38.69 26.08,38.69 26.16,38.77 26.66,38.77 26.76,38.66 26.76,38.4 26.85,38.31 27.03,38.31 27.12,38.4 27.12,38.68 27.21,38.77 28.27,38.77 28.37,38.86 28.37,38.98 28.25,39.1 27.63,39.1 27.54,39.19 27.54,39.36 27.63,39.45 28.33,39.45 28.42,39.54 28.42,39.73 28.34,39.81 27.83,39.81 27.7,39.93 27.7,40.04 27.62,40.12 27.44,40.12 27.37,40.06 27.37,39.71 27.27,39.6 27.08,39.6 26.99,39.69 26.99,40.01 26.92,40.09 26.73,40.09 26.64,40 26.64,39.69 26.55,39.6 26.37,39.6 26.28,39.69 26.28,40.02 26.19,40.11 22.28,40.11 22.19,40.02 22.19,39.72 22.1,39.63 21.76,39.63 21.66,39.53 21.66,39.32 21.75,39.23 v1(22.13,39.23)
V_M_BMC_DDR3_DQ<5>: length 30
  TOP w0.127: v1(25.16,28.81) 25.18,28.81 UT7.K26 ; U2.H8 18.11,39.24 v1(18.13,39.24)
  L3-SIG w0.076: v1(18.13,39.24) 17.86,39.51 17.86,40.27 18.06,40.47 26.05,40.47 26.1,40.42 29.1,40.42 29.23,40.29 29.23,39.59 29.14,39.5 28.81,39.5 28.72,39.41 28.72,39.23 28.81,39.14 29.14,39.14 29.23,39.05 29.23,38.38 28.82,37.98 26.85,37.98 26.76,37.89 26.76,37.47 26.51,37.22 26.13,37.22 26,37.09 26,31.81 26.59,31.22 26.59,29.95 26.41,29.77 26.41,29.47 26.18,29.24 25.85,29.24 25.42,28.81 v1(25.16,28.81)
V_M_BMC_DDR3_DQ<6>: length 23.4
  TOP w0.127: UT7.G27 22.8,29.58 22.8,30.23 23.06,30.49 v1(23.06,30.89) ; U2.G2 v1(22.93,38.43)
  L3-SIG w0.076: v1(23.06,30.89) 23.32,31.16 23.32,31.2 23.57,31.45 23.69,31.45 24.3,30.84 24.43,30.84 24.56,30.97 24.56,31.09 23.95,31.7 23.95,31.83 24.16,32.04 24.32,32.04 24.59,31.77 24.72,31.77 24.9,31.95 24.9,32.07 24.45,32.52 24.45,32.62 24.57,32.73 24.85,32.73 24.94,32.82 24.94,32.96 24.85,33.05 24.56,33.05 24.48,33.13 24.48,33.33 24.53,33.38 24.86,33.38 24.94,33.46 24.94,33.64 24.86,33.71 24.62,33.71 24.53,33.8 24.53,33.98 24.62,34.07 24.85,34.07 24.94,34.16 24.94,34.28 24.85,34.37 24.54,34.37 24.45,34.46 24.45,34.59 24.54,34.68 24.85,34.68 24.94,34.77 24.94,34.89 24.85,34.98 24.54,34.98 24.45,35.07 24.45,35.2 24.54,35.29 24.85,35.29 24.94,35.38 24.94,35.53 24.85,35.62 24.54,35.62 24.45,35.71 24.45,35.83 24.54,35.92 24.85,35.92 24.94,36.01 24.94,36.14 24.85,36.23 24.54,36.23 24.45,36.31 24.45,36.44 24.54,36.53 24.85,36.53 24.94,36.62 24.94,36.77 24.85,36.86 24.54,36.86 24.45,36.95 24.45,37.08 24.54,37.17 24.85,37.17 24.94,37.25 24.94,37.41 24.85,37.5 24.24,37.5 24.15,37.58 24.15,37.74 24.24,37.83 24.62,37.83 24.72,37.93 24.72,38.05 24.62,38.16 24.21,38.16 24.12,38.25 24.12,38.4 24.21,38.49 24.54,38.49 24.63,38.58 24.63,38.75 24.54,38.84 23.34,38.84 v1(22.93,38.43)
V_M_BMC_DDR3_DQ<7>: length 25.1
  TOP w0.127: v1(19.98,31.65) 20.44,31.2 22.5,31.2 22.62,31.07 22.62,30.49 22.38,30.24 UT7.F28 ; U2.H7 v1(18.87,39.28)
  L3-SIG w0.076: v1(19.98,31.65) 20.29,31.35 20.29,30.57 20.2,30.49 20.05,30.49 19.96,30.57 19.96,30.87 19.75,31.07 19.31,31.07 19.22,31.16 19.22,31.69 19.31,31.78 19.55,31.78 19.81,32.03 19.81,36.38 19.5,36.68 19.12,36.68 18.48,37.32 18.48,39.95 18.68,40.14 21.42,40.14 21.51,40.05 21.51,39.72 21.42,39.63 21.31,39.63 21.22,39.54 21.22,39.31 21.13,39.22 20.95,39.22 20.86,39.31 20.86,39.69 20.77,39.78 20.6,39.78 20.51,39.69 20.51,39.31 20.42,39.22 20.24,39.22 20.15,39.31 20.15,39.55 20.06,39.64 19.23,39.64 v1(18.87,39.28)
V_M_BMC_DDR3_DQ<8>: length 24.1
  TOP w0.127: UT7.K25 25.18,28.01 v1(25.16,28.01) ; U2.D7 v1(18.93,36.03)
  L5-SIG w0.076: v1(18.93,36.03) 18.54,36.42 18.54,38.69 18.43,38.79 17.32,38.79 16.91,38.38 16.91,33.36 16.81,33.25 16.81,32.57 17.7,31.68 17.7,31.2 18.26,30.64 18.26,30.59 18.84,30 18.94,30 19.15,29.79 19.15,29.54 19.46,29.23 19.65,29.23 19.95,28.93 19.95,28.74 20.29,28.4 23.79,28.4 23.97,28.22 23.97,27.26 24.07,27.16 24.66,27.16 24.76,27.26 24.76,27.92 24.85,28.01 v1(25.16,28.01)
V_M_BMC_DDR3_DQ<9>: length 24.4
  TOP w0.127: v1(26,28.01) 26,27.99 UT7.L25 ; U2.C3 v1(22.12,36.02)
  L5-SIG w0.076: v1(22.12,36.02) 22.12,36.25 22.52,36.66 22.52,37.08 22.64,37.19 24.38,37.19 24.49,37.08 24.49,36.96 24.61,36.85 24.84,36.85 24.95,36.96 24.95,37.43 25.06,37.55 25.29,37.55 25.41,37.43 25.41,36.96 25.52,36.85 25.75,36.85 25.86,36.96 25.86,37.08 25.98,37.19 27.87,37.19 27.98,37.08 27.98,36.52 28.1,36.4 28.33,36.4 28.44,36.52 28.44,37.08 28.61,37.24 29.29,37.24 29.46,37.08 29.46,33.76 29.28,33.58 29.01,33.58 28.92,33.5 28.92,33.13 29.01,33.05 29.34,33.05 29.46,32.94 29.46,32.72 28.42,31.68 28.42,31.27 28.16,31.02 28.16,30.74 28.01,30.59 28.01,28.61 27.81,28.4 26.37,28.4 26.26,28.29 26.26,28.27 v1(26,28.01)
V_M_BMC_DDR3_DQ<10>: length 21.4
  TOP w0.127: U2.C8 v1(18.13,35.23) ; UT7.J27 v1(24.38,29.61)
  L5-SIG w0.076: v1(24.38,29.61) 24.44,29.67 24.73,29.67 24.8,29.61 24.8,29.25 24.73,29.19 23.23,29.19 23.12,29.3 23.12,29.91 23.03,30 22.87,30 22.78,29.91 22.78,29.28 22.7,29.19 20.05,29.19 19.96,29.28 19.96,29.89 19.87,29.98 19.32,29.98 19.14,30.16 19.14,30.89 18.72,31.31 18.56,31.31 18.53,31.28 18.37,31.28 18.21,31.44 18.21,31.6 18.31,31.71 18.31,31.87 18.2,31.98 18.03,31.98 17.74,32.27 17.27,32.75 17.27,37.51 17.38,37.63 17.62,37.63 17.72,37.52 17.72,35.63 v1(18.13,35.23)
V_M_BMC_DDR3_DQ<11>: length 20.3
  TOP w0.127: v1(26.21,30.97) 25.74,30.97 UT7.J28 ; U2.C2 v1(22.14,35.24)
  L5-SIG w0.076: v1(22.14,35.24) 20.77,36.61 20.77,38.85 20.66,38.97 19.67,38.97 19.55,38.85 19.55,35.62 20.26,34.91 20.26,34.27 22.24,32.29 25.37,32.29 26.21,31.45 v1(26.21,30.97)
V_M_BMC_DDR3_DQ<12>: length 24.2
  TOP w0.127: v1(21.33,34.47) 20.52,34.47 20.07,34.03 U2.A7 ; UT7.M27 v1(26.78,29.61)
  L5-SIG w0.076: v1(21.33,34.47) 21.33,35.49 20.39,36.43 20.39,38.55 20.28,38.66 20.06,38.66 19.93,38.54 19.93,35.77 20.62,35.08 20.62,34.55 22.42,32.75 22.66,32.75 22.78,32.86 22.78,33.47 22.89,33.58 23.12,33.58 23.23,33.47 23.23,32.86 23.35,32.75 25.55,32.75 25.73,32.56 25.89,32.56 26.06,32.73 26.22,32.73 26.38,32.57 26.38,32.41 26.21,32.24 26.21,32.08 26.66,31.63 26.66,30.09 26.78,29.98 v1(26.78,29.61)
V_M_BMC_DDR3_DQ<13>: length 23.2
  TOP w0.127: UT7.M26 v1(26.78,28.81) ; U2.A2 v1(22.94,34.44)
  L5-SIG w0.076: v1(26.78,28.81) 27.21,29.24 27.21,29.87 27.35,30 27.62,30 27.7,30.09 27.7,31.22 27.95,31.46 27.95,31.77 27.58,32.14 27.58,32.56 27.69,32.67 28.33,32.67 28.44,32.79 28.44,33.01 28.33,33.13 27.69,33.13 27.58,33.24 27.58,34.07 27.69,34.18 28.5,34.18 28.62,34.3 28.62,34.53 28.5,34.64 27.36,34.64 27.25,34.76 27.25,34.98 27.36,35.1 28.38,35.1 28.49,35.21 28.49,35.44 28.38,35.56 27.69,35.56 27.58,35.67 27.58,36.18 27.35,36.4 25.72,36.4 25.61,36.29 25.61,36.07 25.49,35.96 25.27,35.96 25.15,36.07 25.15,36.29 25.04,36.4 24.81,36.4 24.69,36.29 24.69,36.07 24.58,35.96 24.35,35.96 24.24,36.07 24.24,36.29 24.12,36.4 22.73,36.4 22.55,36.23 22.55,34.83 v1(22.94,34.44)
V_M_BMC_DDR3_DQ<14>: length 22.9
  TOP w0.127: UT7.M28 26.84,30.34 26.84,31.04 26.49,31.4 25.34,31.4 v1(24.99,31.04) ; U2.B8 v1(18.13,34.43)
  L5-SIG w0.076: v1(18.13,34.43) 17.85,34.15 17.68,34.15 17.6,34.07 17.6,33.25 17.86,32.99 18.02,32.99 18.66,33.63 18.82,33.63 19.01,33.44 19.01,33.28 18.37,32.64 18.37,32.47 18.54,32.31 18.71,32.31 19.34,32.94 19.51,32.94 19.67,32.78 19.67,32.61 19.04,31.98 19.04,31.81 19.16,31.69 19.39,31.69 19.98,32.29 20.19,32.29 20.61,31.87 20.61,31.64 20.08,31.12 20.08,30.47 20.2,30.36 20.48,30.36 20.59,30.47 20.59,30.95 20.76,31.12 21.47,31.12 21.58,31.01 21.58,30.08 21.69,29.97 21.92,29.97 22.04,30.08 22.04,30.19 22.15,30.31 23.89,30.31 24.17,30.03 24.83,30.03 24.99,30.18 v1(24.99,31.04)
V_M_BMC_DDR3_DQ<15>: length 21.2
  TOP w0.127: v1(27.3,30.64) 27.65,30.29 27.7,30.29 UT7.N28 ; U2.A3 v1(22.13,33.63)
  L5-SIG w0.076: v1(22.13,33.63) 22.57,34.07 23.11,34.07 23.31,34.27 23.31,35.44 23.46,35.59 24.09,35.59 24.2,35.48 24.2,33.42 24.32,33.3 24.55,33.3 24.66,33.42 24.66,35.4 24.77,35.51 25,35.51 25.12,35.4 25.12,33.42 25.23,33.3 25.46,33.3 25.57,33.42 25.57,35.48 25.69,35.59 26.61,35.59 26.79,35.41 26.79,32.8 27.13,32.45 27.13,30.8 v1(27.3,30.64)
V_M_BMC_DDR3_DQ<16>: length 30.8
  TOP w0.127: v1(29.53,37.62) 29.95,37.2 U3.E3 ; UT7.N24 v1(27.58,27.21)
  L10-SIG w0.076: v1(29.53,37.62) 29.18,37.27 28.61,37.27 28.52,37.18 28.52,32.34 28.9,31.96 28.9,30.33 28.95,30.28 28.95,25.53 28.75,25.33 28.28,25.33 28.19,25.42 28.19,26.28 28.1,26.37 27.92,26.37 27.83,26.28 27.83,25.42 27.74,25.33 27.57,25.33 27.48,25.42 27.48,26.28 27.39,26.37 27.21,26.37 27.12,26.28 27.12,25.42 27.03,25.33 26.85,25.33 26.76,25.42 26.76,26.28 26.68,26.37 26.5,26.37 26.41,26.28 26.41,25.42 26.32,25.33 26.14,25.33 26.05,25.42 26.05,26.28 25.96,26.37 25.79,26.37 25.7,26.28 25.7,25.42 25.61,25.33 25.39,25.33 25.29,25.43 25.29,26.65 25.47,26.83 27.2,26.83 v1(27.58,27.21)
V_M_BMC_DDR3_DQ<17>: length 30.2
  TOP w0.127: U3.F7 v1(27.97,37.6) ; UT7.N25 v1(27.58,28.01)
  L10-SIG w0.076: v1(27.58,28.01) 27.21,28.38 26.47,28.38 26.38,28.29 26.38,27.68 26.47,27.59 27.83,27.59 28.01,27.41 28.01,26.97 28.15,26.83 28.61,26.83 28.75,26.97 28.75,28.3 28.59,28.45 28.06,28.45 27.98,28.53 27.98,29.1 28.07,29.19 28.62,29.19 28.75,29.32 28.75,29.85 28.59,30 28.1,30 28.01,30.09 28.01,30.59 28.21,30.79 28.35,30.79 28.44,30.88 28.44,31.16 28.35,31.25 28.15,31.25 28.06,31.33 28.06,31.51 28.15,31.6 28.35,31.6 28.44,31.69 28.44,31.87 28.16,32.15 28.16,32.6 28.07,32.69 27.77,32.69 27.68,32.78 27.68,32.96 27.77,33.05 28.07,33.05 28.16,33.14 28.16,33.35 28.07,33.44 27.72,33.44 27.63,33.53 27.63,33.71 27.72,33.8 28.2,33.8 28.29,33.89 28.29,34.06 28.2,34.15 26.88,34.15 26.79,34.24 26.79,34.42 26.88,34.51 28.2,34.51 28.29,34.6 28.29,34.77 28.2,34.86 26.9,34.86 26.82,34.95 26.82,35.13 26.9,35.22 28.2,35.22 28.29,35.31 28.29,35.49 28.2,35.57 26.88,35.57 26.79,35.66 26.79,36.37 26.88,36.45 28.12,36.45 28.21,36.54 28.21,36.74 28.12,36.83 27.72,36.83 27.63,36.92 27.63,37.26 v1(27.97,37.6)
V_M_BMC_DDR3_DQ<18>: length 25.9
  TOP w0.127: UT7.T28 30.38,30.03 30.75,30.41 v1(30.75,30.43) ; U3.F2 v1(31.99,37.63)
  L10-SIG w0.076: v1(31.99,37.63) U3.F2 33.22,38 33.32,38.11 33.32,38.44 33.39,38.51 33.85,38.51 33.95,38.41 33.95,37.7 34.04,37.61 34.8,37.61 34.89,37.52 34.89,37.34 34.8,37.25 34.04,37.25 33.95,37.17 33.95,36.99 34.04,36.9 34.8,36.9 34.89,36.81 34.89,36.63 34.8,36.54 34.04,36.54 33.95,36.45 33.95,36.28 34.04,36.19 34.8,36.19 34.89,36.1 34.89,35.92 34.8,35.83 33.94,35.83 33.85,35.74 33.85,35.57 33.94,35.48 34.8,35.48 34.89,35.39 34.89,35.21 34.8,35.12 34.04,35.12 33.95,35.03 33.95,34.85 34.04,34.77 34.8,34.77 34.89,34.68 34.89,34.5 34.8,34.41 34.04,34.41 33.95,34.32 33.95,34.14 34.04,34.05 34.8,34.05 34.89,33.97 34.89,33.79 34.8,33.7 34.04,33.7 33.95,33.61 33.95,32.31 33.78,32.15 33.66,32.15 33.14,32.67 33.01,32.67 32.89,32.54 32.89,32.42 33.41,31.89 33.41,31.77 31.72,30.08 31.11,30.08 v1(30.75,30.43)
V_M_BMC_DDR3_DQ<19>: length 25.5
  TOP w0.127: U3.F8 v1(27.17,37.6) ; UT7.U28 31.18,30.84 31.05,30.97 28.16,30.97 v1(27.53,31.6)
  L10-SIG w0.076: v1(27.53,31.6) 27.25,31.6 26,32.85 26,35 25.91,35.09 24.54,35.09 24.45,35.17 24.45,35.35 24.54,35.44 25.91,35.44 26,35.53 26,35.71 25.91,35.8 24.54,35.8 24.45,35.89 24.45,36.06 24.54,36.15 25.91,36.15 26,36.24 26,36.42 25.91,36.51 24.54,36.51 24.45,36.6 24.45,36.77 24.54,36.86 25.91,36.86 26,36.95 26,37.13 25.91,37.22 24.54,37.22 24.45,37.31 24.45,37.49 24.54,37.57 25.91,37.57 26,37.66 26,37.89 26.09,37.98 27.08,37.98 27.17,37.89 v1(27.17,37.6)
V_M_BMC_DDR3_DQ<20>: length 29.6
  TOP w0.127: U3.H3 v1(30.88,39.6) ; UT7.N26 v1(27.58,28.81)
  L10-SIG w0.076: v1(30.88,39.6) 31.17,39.9 33.84,39.9 33.93,39.98 33.93,40.3 33.84,40.39 25.42,40.39 25.22,40.19 25.22,39.68 24.38,38.84 23.46,38.84 23.31,38.69 23.31,32.82 23.79,32.34 25.37,32.34 26.68,31.03 26.68,30.45 26.41,30.18 26.41,29.27 26.49,29.19 27.2,29.19 v1(27.58,28.81)
V_M_BMC_DDR3_DQ<21>: length 29.9
  TOP w0.127: U3.H8 v1(27.17,39.2) ; UT7.N27 v1(27.58,29.61)
  L10-SIG w0.076: v1(27.58,29.61) 27.58,29.98 27.65,30.06 27.65,31.01 27.57,31.1 27.15,31.1 25.52,32.72 25.52,33.09 25.43,33.18 24.24,33.18 24.15,33.27 24.15,33.49 24.24,33.57 25.61,33.57 25.7,33.66 25.7,33.84 25.61,33.93 24.24,33.93 24.15,34.02 24.15,34.2 24.24,34.29 25.61,34.29 25.7,34.37 25.7,34.55 25.61,34.64 24.24,34.64 24.15,34.73 24.15,37.89 24.24,37.98 25.6,37.98 25.7,38.08 25.7,38.25 25.61,38.33 24.8,38.33 24.71,38.42 24.71,38.6 24.8,38.69 25.43,38.69 25.52,38.78 25.52,39.95 25.61,40.04 25.83,40.04 25.91,39.95 25.91,39.67 26,39.58 26.18,39.58 26.27,39.67 26.27,39.97 26.36,40.06 26.57,40.06 26.66,39.97 26.66,39.67 26.75,39.58 26.93,39.58 27.02,39.67 27.02,39.97 27.11,40.06 27.29,40.06 27.37,39.97 27.37,39.67 27.46,39.58 27.64,39.58 27.73,39.67 27.73,39.97 27.82,40.06 28.21,40.06 28.42,39.86 28.42,39.29 28.24,39.12 27.25,39.12 v1(27.17,39.2)
V_M_BMC_DDR3_DQ<22>: length 29.1
  TOP w0.127: UT7.R27 v1(29.98,29.61) ; U3.G2 v1(31.98,38.41)
  L10-SIG w0.076: v1(29.98,29.61) 30.35,29.98 30.35,31.15 30.45,31.25 30.45,32.15 30.54,32.24 30.75,32.24 30.84,32.15 30.84,30.96 30.93,30.87 31.11,30.87 31.2,30.96 31.2,32.15 31.29,32.24 31.46,32.24 31.55,32.15 31.55,30.96 31.64,30.87 31.82,30.87 31.91,30.96 31.91,32.15 32,32.24 32.3,32.24 32.4,32.34 32.4,32.52 32.33,32.59 30.18,32.59 30.09,32.68 30.09,32.89 30.18,32.97 32.29,32.97 32.38,33.06 32.38,33.89 32.51,34.02 32.72,34.02 32.81,33.93 32.81,33.57 32.87,33.51 33.14,33.51 33.22,33.58 33.22,34.78 33.14,34.85 32.48,34.85 32.38,34.96 32.38,35.49 32.48,35.59 33.06,35.59 33.19,35.72 33.19,36.23 33.06,36.35 31.72,36.35 31.63,36.44 31.63,36.69 31.74,36.81 33.15,36.81 33.24,36.9 33.24,37.1 33.15,37.19 31.82,37.19 31.57,37.45 31.57,38 v1(31.98,38.41)
V_M_BMC_DDR3_DQ<23>: length 25.1
  TOP w0.127: U3.H7 29.16,38.82 29.23,38.82 v1(29.64,38.41) ; UT7.V27 32.38,29.61 v1(32.4,29.61)
  L10-SIG w0.076: v1(32.4,29.61) 32.28,29.73 32.28,30.08 35.25,33.05 35.25,33.67 35.34,33.76 35.85,33.76 35.93,33.85 35.93,34.03 35.85,34.12 35.34,34.12 35.25,34.21 35.25,34.42 35.34,34.51 35.71,34.51 35.8,34.6 35.8,34.78 35.71,34.87 35.34,34.87 35.25,34.96 35.25,35.13 35.34,35.22 35.71,35.22 35.8,35.31 35.8,35.49 35.71,35.58 35.34,35.58 35.25,35.67 35.25,35.84 35.34,35.93 35.71,35.93 35.8,36.02 35.8,36.2 35.71,36.29 35.34,36.29 35.25,36.38 35.25,36.56 35.34,36.65 35.71,36.65 35.8,36.73 35.8,36.91 35.71,37 35.34,37 35.25,37.09 35.25,37.27 35.34,37.36 35.71,37.36 35.8,37.45 35.8,37.62 35.71,37.71 35.34,37.71 35.25,37.8 35.25,37.98 35.34,38.07 35.71,38.07 35.8,38.16 35.8,38.33 35.71,38.42 35.34,38.42 35.25,38.51 35.25,38.73 35.16,38.82 30.04,38.82 v1(29.64,38.41)
V_M_BMC_DDR3_DQ<24>: length 30.9
  TOP w0.127: U3.D7 28.83,36.86 v1(28.9,36.86) ; UT7.R26 v1(29.98,28.81)
  L3-SIG w0.076: v1(28.9,36.86) 29.1,36.86 29.25,37.01 30.09,37.01 30.42,37.34 30.42,39.95 30.31,40.06 30.08,40.06 29.99,39.97 29.99,38.16 29.86,38.03 29.36,38.03 29.18,37.85 29.18,37.45 28.97,37.24 28.56,37.24 28.47,37.15 28.47,36.81 28.38,36.72 28.1,36.72 28.01,36.81 28.01,37.15 27.92,37.24 27.7,37.24 27.6,37.14 27.6,36.53 27.5,36.43 26.88,36.43 26.79,36.34 26.79,35.61 26.88,35.52 28.33,35.52 28.42,35.43 28.42,35.25 28.33,35.17 26.9,35.17 26.82,35.08 26.82,34.87 26.9,34.78 28.24,34.78 28.37,34.65 28.37,34.36 28.28,34.27 28,34.27 27.91,34.18 27.91,34 28,33.91 28.3,33.91 28.39,33.83 28.39,33.65 28.3,33.56 28,33.56 27.91,33.47 27.91,32.43 27.82,32.34 27.21,32.34 27.12,32.25 27.12,32.07 27.21,31.98 28,31.98 28.09,31.9 28.09,31.31 28,31.22 27.58,31.22 27.48,31.12 27.48,30.96 27.57,30.87 27.9,30.87 27.98,30.78 27.98,30.56 27.9,30.47 27.77,30.47 27.68,30.38 27.68,30.21 27.77,30.12 27.9,30.12 27.98,30.03 27.98,29.36 28.12,29.22 28.54,29.22 28.95,28.81 v1(29.98,28.81)
V_M_BMC_DDR3_DQ<25>: length 30.9
  TOP w0.104: U3.C3 30.02,34.05 v1(29.09,34.05)
  TOP w0.127: UT7.R25 v1(29.98,28.01)
  L3-SIG w0.076: v1(29.98,28.01) 29.98,27.64 29.9,27.56 29.69,27.56 29.56,27.69 29.56,28.39 29.47,28.48 29.29,28.48 29.2,28.39 29.2,27.23 29.1,27.13 28.87,27.13 28.8,27.21 28.8,28.25 28.67,28.38 28.06,28.38 27.98,28.3 27.98,27.68 27.9,27.59 27.47,27.59 27.23,27.35 27.23,26.95 27.35,26.83 28.86,26.83 28.95,26.74 28.95,26.51 28.86,26.42 27.92,26.42 27.83,26.33 27.83,26.13 27.92,26.04 29.06,26.04 29.14,25.96 29.14,25.75 29.03,25.63 28.37,25.63 28.29,25.56 28.29,25.38 28.39,25.28 29,25.28 29.15,25.13 29.15,24.66 29.22,24.59 29.55,24.59 29.61,24.66 29.61,26.6 29.79,26.78 30.17,26.78 30.35,26.95 30.35,29.09 30.19,29.24 28.85,29.24 28.75,29.34 28.75,33.89 28.91,34.05 v1(29.09,34.05)
V_M_BMC_DDR3_DQ<26>: length 24.4
  TOP w0.127: U3.C8 v1(28,36.03) ; UT7.AA28 34.38,30.16 v1(34.78,30.56)
  L3-SIG w0.076: v1(28,36.03) 28.45,36.48 29.13,36.48 29.37,36.72 30.23,36.72 30.75,37.24 30.75,38.64 32.48,40.37 35.88,40.37 36.52,39.73 36.52,39.07 36.77,38.82 37.2,38.82 37.31,38.72 37.31,37.95 37.39,37.87 37.62,37.87 37.71,37.78 37.71,37.6 37.62,37.51 37.39,37.51 37.31,37.42 37.31,33.41 36.52,32.62 36.09,32.62 35.2,31.73 35.2,30.98 v1(34.78,30.56)
V_M_BMC_DDR3_DQ<27>: length 25.8
  TOP w0.127: v1(33.15,28.01) 33.15,28.03 UT7.W26 ; U3.C2 v1(31.99,35.99)
  L3-SIG w0.076: v1(31.99,35.99) 32.38,36.38 33.09,36.38 33.22,36.25 33.22,35.84 32.96,35.59 32.51,35.59 32.38,35.46 32.38,34.08 32.47,33.99 33.88,33.99 33.99,34.11 33.99,35.17 34.08,35.26 34.42,35.26 34.51,35.17 34.51,33.66 34.11,33.25 32.52,33.25 32.43,33.17 32.43,32.99 32.52,32.9 33.74,32.9 33.83,32.81 33.83,32.66 33.74,32.57 32.82,32.57 32.73,32.48 32.73,32.31 32.82,32.22 33.58,32.22 33.67,32.13 33.67,31.95 33.58,31.86 32.82,31.86 32.73,31.77 32.73,31.59 32.82,31.51 33.48,31.51 33.57,31.42 33.57,31.24 33.48,31.15 32.82,31.15 32.73,31.06 32.73,30.21 32.94,30 33.37,30 33.52,29.85 33.52,29.75 33.6,29.67 33.79,29.67 33.88,29.58 33.88,29.29 33.79,29.2 32.82,29.2 32.73,29.11 32.73,28.93 32.82,28.84 33.43,28.84 33.52,28.75 33.52,28.37 v1(33.15,28.01)
V_M_BMC_DDR3_DQ<28>: length 30.7
  TOP w0.127: UT7.R24 v1(29.98,26.41) ; v1(27.2,33.03) 27.48,33.3 27.67,33.3 U3.A7
  L3-SIG w0.076: v1(29.98,26.41) 29.98,24.76 30.4,24.34 30.4,22.94 30.24,22.79 29.61,22.79 29.48,22.66 29.48,22.33 29.41,22.26 29.13,22.26 29.05,22.33 29.05,22.59 28.86,22.78 28.05,22.78 27.96,22.87 27.96,23.45 28.11,23.6 29.52,23.6 29.61,23.69 29.61,24 29.52,24.08 28.84,24.08 28.75,24.17 28.75,24.3 28.66,24.39 28.03,24.39 27.96,24.47 27.96,25.1 27.78,25.28 27.78,25.61 26.36,27.03 26.36,27.34 26.61,27.59 26.99,27.59 27.17,27.77 27.17,28.34 27.08,28.43 26.7,28.43 26.35,28.07 26.35,27.75 26.26,27.66 25.85,27.66 25.57,27.94 25.57,28.28 25.72,28.43 26.26,28.43 26.43,28.6 26.43,28.95 26.67,29.19 26.99,29.19 27.17,29.37 27.17,29.8 26.94,30.03 26.94,31.43 26.76,31.6 26.76,34.12 26.87,34.22 27.46,34.22 27.55,34.13 27.55,33.38 v1(27.2,33.03)
V_M_BMC_DDR3_DQ<29>: length 30.9
  TOP w0.112: v1(30.04,31.93) 29.16,31.93 29.05,32.04 29.05,32.36 29.16,32.47 32.28,32.47 32.33,32.52 32.33,32.82 32.25,32.9 29.18,32.9 29.08,33 29.08,33.28 29.18,33.38 32.12,33.38 32.37,33.64 U3.A2
  TOP w0.127: UT7.T24 v1(30.78,26.41)
  L3-SIG w0.076: v1(30.04,31.93) 29.61,31.93 29.46,32.09 29.46,33.55 29.37,33.64 29.19,33.64 29.1,33.55 29.1,31.56 29.19,31.47 30.18,31.47 30.27,31.38 30.27,31.2 30.18,31.11 29.94,31.11 29.85,31.03 29.85,30.85 29.76,30.76 29.58,30.76 29.5,30.85 29.5,31.03 29.41,31.11 29.19,31.11 29.1,31.03 29.1,30.16 29.25,30 31.04,30 31.13,29.91 31.13,29.26 31.04,29.17 30.71,29.17 30.63,29.08 30.63,28.9 30.71,28.81 31.04,28.81 31.13,28.73 31.13,27.74 30.65,27.26 30.65,26.83 30.4,26.57 30.4,25.31 30.49,25.22 30.66,25.22 30.78,25.33 v1(30.78,26.41)
V_M_BMC_DDR3_DQ<30>: length 24.8
  TOP w0.089: UT7.Y27 34,29.63 v1(34,30.46)
  TOP w0.104: v1(31.08,36.71) 28.8,34.42 27.95,34.42 U3.B8
  L3-SIG w0.076: v1(34,30.46) 34.41,30.87 34.41,32.11 35.78,33.48 35.78,38.26 35.63,38.41 34.52,38.41 34.44,38.5 34.44,39.26 34.35,39.35 34.12,39.35 34.03,39.26 34.03,36.63 33.83,36.43 33.45,36.43 33.17,36.71 32.7,36.71 32.61,36.8 32.61,37.15 32.52,37.24 32.35,37.24 32.26,37.15 32.26,36.8 32.17,36.71 31.99,36.71 31.9,36.8 31.9,37.15 31.81,37.24 31.64,37.24 31.55,37.15 31.55,36.8 31.46,36.71 v1(31.08,36.71)
V_M_BMC_DDR3_DQ<31>: length 24.6
  TOP w0.127: v1(32.81,34.4) 31.97,34.4 U3.A3 ; UT7.AA27 v1(34.78,29.61)
  L3-SIG w0.076: v1(32.81,34.4) 33.14,34.4 33.2,34.46 33.2,35.4 33.45,35.64 33.85,35.64 34.33,36.12 34.33,37.97 34.42,38.05 35.39,38.05 35.48,37.97 35.48,37.72 35.39,37.64 34.78,37.64 34.69,37.55 34.69,37.37 34.78,37.28 35.39,37.28 35.48,37.19 35.48,37.01 35.39,36.92 34.78,36.92 34.69,36.84 34.69,36.66 34.78,36.57 35.39,36.57 35.48,36.48 35.48,36.3 35.39,36.21 34.78,36.21 34.69,36.12 34.69,35.95 34.78,35.86 35.39,35.86 35.48,35.77 35.48,35.32 35.39,35.24 34.93,35.24 34.84,35.15 34.84,34.98 34.93,34.89 35.44,34.89 35.53,34.8 35.53,34.62 35.44,34.53 34.93,34.53 34.84,34.44 34.84,34.27 34.93,34.18 35.44,34.18 35.53,34.09 35.53,33.91 35.44,33.82 34.93,33.82 34.84,33.73 34.84,33.08 34.05,32.29 34.05,31.02 33.93,30.89 33.75,30.89 33.57,30.71 33.57,30.23 33.7,30.1 33.8,30.1 34.3,29.61 v1(34.78,29.61)
V_M_BMC_DDR3_DQ<32>: length 40.5
  TOP w0.127: U4.E3 40.43,37.16 40.18,36.91 40.18,33.58 40.02,33.43 39.77,33.43 39.64,33.56 39.64,34.07 39.52,34.19 39.19,34.19 39.06,34.32 39.06,34.57 39.19,34.7 39.52,34.7 39.64,34.83 39.64,35.08 39.52,35.21 39.19,35.21 39.06,35.34 39.06,35.59 39.19,35.72 39.52,35.72 39.64,35.84 39.64,36.1 39.52,36.23 39.19,36.23 39.06,36.35 39.06,36.61 39.19,36.73 39.52,36.73 39.64,36.86 39.64,37.45 39.16,37.93 39.16,38.51 v1(38.58,39.1) ; UT7.T26 v1(30.78,28.01)
  L5-SIG w0.076: v1(30.78,28.01) 30.38,28.4 29.76,28.4 29.61,28.25 29.61,25.86 29.51,25.76 29.27,25.76 29.15,25.88 29.15,30.16 30,31 30.43,31 31.08,31.65 31.08,36.07 31.59,36.58 31.59,38.79 31.74,38.94 32.31,38.94 32.48,38.77 33.83,38.77 34.18,39.12 35.53,39.12 35.88,38.77 38.25,38.77 v1(38.58,39.1)
